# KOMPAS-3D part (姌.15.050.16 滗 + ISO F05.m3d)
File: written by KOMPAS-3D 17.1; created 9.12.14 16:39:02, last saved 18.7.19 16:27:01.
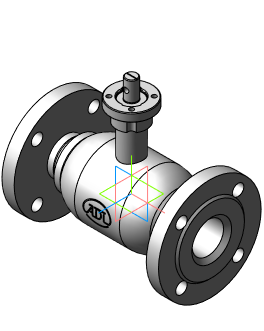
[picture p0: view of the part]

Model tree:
1. Операция без истории:3  (labels: Сталь 20  ГОСТ 1050-88)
